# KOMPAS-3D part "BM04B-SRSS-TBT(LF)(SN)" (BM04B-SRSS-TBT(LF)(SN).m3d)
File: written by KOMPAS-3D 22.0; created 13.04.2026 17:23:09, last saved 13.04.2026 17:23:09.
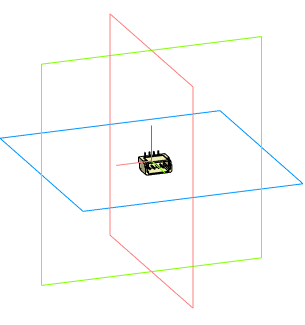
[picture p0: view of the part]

Document properties: Автор: Andrey; Полное имя файла: C:\Users\User1\Documents\BM04B-SRSS-TBT(LF)(SN).m3d

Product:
- Part/product: BM04B-SRSS-TBT(LF)(SN)

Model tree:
1. Операция без истории:1
2. Операция без истории:2
3. Операция без истории:3
4. Операция без истории:4
5. Операция без истории:5
6. Операция без истории:6
7. Операция без истории:7
8. Операция без истории:8
9. Операция без истории:9
10. Операция без истории:10
11. Операция без истории:11
12. Операция без истории:12
13. Операция без истории:13
14. Операция без истории:14
15. Операция без истории:15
